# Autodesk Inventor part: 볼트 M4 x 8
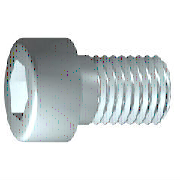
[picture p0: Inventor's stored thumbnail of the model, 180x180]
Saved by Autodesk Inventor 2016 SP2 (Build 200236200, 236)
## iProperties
IsCustomPart: 1
Created: 2012-02
Part Number: 볼트 M4 x 8
Material: 스테인리스강
Description: 6각 소켓 머리 캡 나사
Document SubType Name: Modeling
Standard: ISO 4762
Designer: mduedu
Standard Revision: Fourth edition 2004-03-01
Standards Organization: ISO
Language: ko-KR
Size Designation: M4 x 8
Categories: <MemberInstance><Categories><Category DisplayName="조임쇠" InternalName="e4da775c-781d-43d5-af7c-5136215cf5a6" Mnemonic="FSTN"><Category DisplayName="볼트" InternalN
Density: 7.75 g/cm^3
Appearance: 반광택
Author: mduedu
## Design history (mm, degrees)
sketch "스케치1"
  geometry: L1 (-1, 0)-(8, 0); L2 (8, 0)-(8, 2); L3 (8, 2)-(1.75, 2); L4 (1.75, 2)-(1.32, 2); L5 (1.32, 2)-(0, 2); L6 (0, 2)-(0, 3.5); L7 (0, 3.5)-(-4, 3.5); L8 (-4, 3.5)-(-4, 1.732); L9 (-4, 1.732)-(-2, 1.732); L10 (-2, 1.732)-(-1, 0); L11 (-6.4, 0)-(10.4, 0) reference; L12 (0, -0.7)-(0, 4.2) reference; L13 (1.75, 2)-(0, 2)
  constraints: 22 end point, 6 parallel, 2 collinear, 2 perpendicular, 1 horizontal, 1 point on line
  dimensions: "d1" = 6.25 distance from line of L3.end L2 (= GEL); "d2" = 0.42952 distance of L4.end L3.end (computed from GAL); "d3" = 4 distance between parallel lines of L8 L6 (= KOH); "d4" = 2 distance of L8.end L9.end (= INTI); "d5" = 60 deg angle of L10 L1; "d6" = 4 diameter of L3 L1 (= GD); "d7" = 4 diameter of L5 L1 (= BDM); "d8" = 3.4641 diameter of L9 L1 (= 1.1547 x SW); "d9" = 7 diameter of L7 L1 (= KOD); "d26" = 8 distance between parallel lines of L12 L2 (= NLG)
revolve "본체" sketch "스케치1" stored, may be unused: angle "d10" = 90 deg
sketch "스케치2"
  geometry: L1 (0, -4.9)-(0, 4.9) reference; L2 (-4.9, 0)-(4.9, 0) reference; L3 (1.732, 0)-(0.866, -1.5); L4 (0.866, -1.5)-(-0.866, -1.5); L5 (-0.866, -1.5)-(-1.732, 0); L6 (-1.732, 0)-(-0.866, 1.5); L7 (-0.866, 1.5)-(0.866, 1.5); L8 (0.866, 1.5)-(1.732, 0); 2 further points
  constraints: 12 end point, 1 coincident, 1 horizontal alignment, 1 point on line, 12 other
extrude "슬롯" join sketch "스케치2" stored distance "d11" = 10; taper "d12" = 0 deg
workplane "Work Plane1"
fillet "Fillet2" dims "d30" = 0.1 (= R)
body "Solid1"
fillet "모깎기1" dims "d17" = 0.4 (= RR)
feature "스레드" dims "d13" = 6.25 (= GEL), "d14" = 0
chamfer "모따기1" distance "d15" = 0.42941 (= -0.5 x SPD + 0.5 x GD); stored, may be unused: second distance "d16" = 0.42941 (= GUL), angle "d27" = 45 deg
other parameters: "GD" = 4 [user parameter; used in 2 equation terms], "NLG" = 8 [user parameter; used in 1 equation term], "GEL" = 6.25 [user parameter; used in 2 equation terms], "KOD" = 7 [user parameter; used in 1 equation term], "KOH" = 4 [user parameter; used in 1 equation term], "INTI" = 2 [user parameter; used in 1 equation term], "GAL" = 0.42941 (= 0.61345 x PTC) [user parameter; used in 1 equation term], "GUL" = 0.42941 (= 0.61345 x PTC) [user parameter; used in 1 equation term], "BDM" = 4 (= NND) [user parameter; used in 1 equation term], "SW" = 3 [user parameter; used in 2 equation terms], "RR" = 0.4 [user parameter; used in 1 equation term], "SPD" = 3.14117 (= NND - 1.2269 x PTC) [user parameter; used in 1 equation term], "d19" = 0, "d28" = 0, "d29" = 0, "R" = 0.1 [user parameter; used in 1 equation term], "TOA" = 30 deg [user parameter], "GD1" = 3.14117 (= THREADDIA - 1.2269 x PTC) [user parameter], "THREADDIA" = 4 [user parameter; used in 1 equation term], "FAWI" = 45 deg [user parameter], "TPU" = 14.28571 (computed from PTC) [user parameter], "PTC" = 0.7 [user parameter; used in 5 equation terms], "NND" = 4 [user parameter; used in 2 equation terms], "E0" = 3.465 (= 1.155 x SW) [user parameter]
